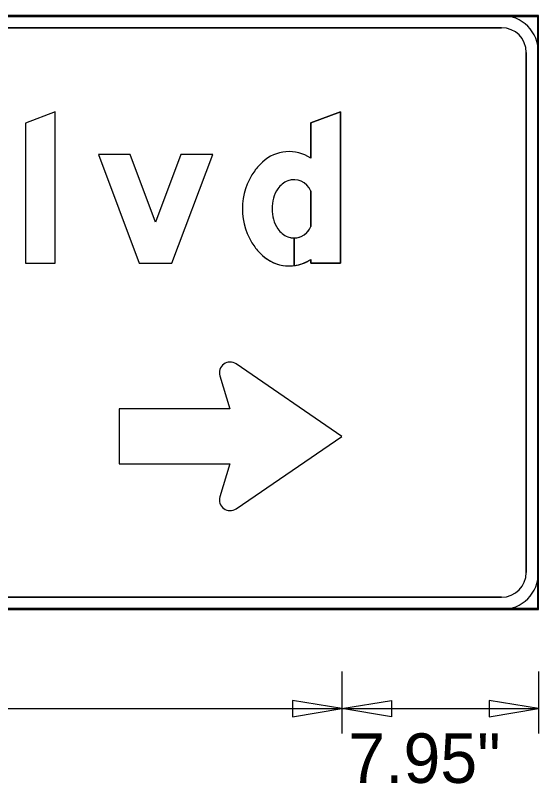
# Model space of a CAD drawing. Extents: x 1374 to 1480, y 568 to 638.
# Drawn here: x 1448.353 to 1450.115, y 598.164 to 600.75 of the extents above; entities that cross this region are included whole.
import ezdxf

# ---------------------------------------------------------------- set-up
doc = ezdxf.new("R2010")
doc.units = 0
for name, color, linetype in [('GSBWFill', 7, 'Continuous'), ('GSColorFill', 7, 'Continuous'), ('GSDims', 7, 'Continuous'), ('GSOutline', 7, 'Continuous')]:
    doc.layers.add(name, color=color, linetype=linetype)

msp = doc.modelspace()

# ---------------------------------------------------------------- linework, layer by layer
at = {"layer": 'GSBWFill'}
for p, q in [((1450.1146, 600.7496), (1441.1146, 600.7496)), ((1449.9896, 600.7496), (1441.2396, 600.7496)), ((1450.1146, 598.7496), (1450.1146, 600.7496)), ((1441.2396, 600.7079), (1449.9896, 600.7079)), ((1450.073, 600.6246), (1450.073, 598.8746)), ((1450.1146, 598.8746), (1450.1146, 600.6246)), ((1449.3471, 600.1585), (1449.3471, 600.0386)), ((1449.2913, 600.0005), (1449.2913, 599.9071)), ((1449.2913, 599.9071), (1449.2913, 600.0005)), ((1449.9896, 598.7912), (1441.24, 598.7912)), ((1441.1146, 598.7496), (1450.1146, 598.7496)), ((1441.24, 598.7496), (1449.9896, 598.7496))]:
    msp.add_line(p, q, dxfattribs=at)
for points in [[(1448.4871, 599.916), (1448.4871, 600.4248), (1448.3871, 600.3869), (1448.3871, 599.916)], [(1448.739, 600.281), (1448.6321, 600.281), (1448.7696, 599.916), (1448.8796, 599.916), (1449.0171, 600.281), (1448.9103, 600.281), (1448.8246, 600.0537)]]:
    msp.add_lwpolyline(points, close=True, dxfattribs=at)
for points in [[(1449.3471, 599.928), (1449.3471, 599.916), (1449.4471, 599.916), (1449.4471, 600.4248), (1449.3471, 600.3879), (1449.3471, 600.2691)], [(1449.0962, 599.089), (1449.4521, 599.3327), (1449.0962, 599.5764)], [(1449.0413, 599.536), (1449.0753, 599.4255), (1448.7021, 599.4255)], [(1448.7021, 599.4255), (1448.7021, 599.2399), (1449.0753, 599.2399), (1449.0413, 599.1294)]]:
    msp.add_lwpolyline(points, dxfattribs=at)
for centre, radius, start, end in [((1449.9896, 600.6246), 0.125, 0, 90), ((1449.9896, 600.6246), 0.0833, 0, 90), ((1449.0758, 599.5466), 0.0361, 55.6003, 197.0573), ((1449.0758, 599.1188), 0.0361, 162.9427, 304.3997), ((1449.9896, 598.8746), 0.125, 270, 0), ((1449.9896, 598.8746), 0.0833, 270, 0)]:
    msp.add_arc(centre, radius, start, end, dxfattribs=at)
for centre, major_axis, start_param, end_param in [((1449.2746, 600.1601), (0, 0.1309), 5.696193, 7.034788), ((1449.2879, 600.1351), (0, 0.1584), 0.704703, 0.952762), ((1449.3358, 600.0985), (0, 0.2187), 0.943678, 1.570796), ((1449.2948, 600.1272), (0, 0.07), 0.364208, 0.979941), ((1449.2913, 600.1365), (0, 0.06), 5.086447, 6.647393), ((1449.3326, 600.1019), (0, 0.1155), 0.979941, 1.599528), ((1449.3358, 600.0985), (0, 0.2187), 1.570796, 2.197914), ((1449.3326, 600.0952), (0, 0.1155), 1.542065, 2.161651), ((1449.2913, 600.0605), (0, 0.06), 3.142009, 4.338331), ((1449.2948, 600.0699), (0, 0.07), 2.161651, 2.777385), ((1449.2913, 600.0605), (0, 0.06), 2.777385, 3.141593), ((1449.2879, 600.062), (0, 0.1584), 2.188831, 2.436889), ((1449.2746, 600.037), (0, 0.1309), 2.38999, 3.269164), ((1449.2746, 600.037), (0, 0.1309), 3.269357, 3.728585)]:
    msp.add_ellipse(centre, major_axis=major_axis, ratio=0.999997, start_param=start_param, end_param=end_param, dxfattribs=at)
at = {"layer": 'GSColorFill'}
for p, q in [((1450.1146, 600.7496), (1441.1146, 600.7496)), ((1450.1146, 600.7496), (1441.1146, 600.7496)), ((1441.1188, 600.7454), (1450.1105, 600.7454)), ((1449.9896, 600.7496), (1441.2396, 600.7496)), ((1450.1105, 600.7454), (1450.1105, 598.7537)), ((1450.1146, 598.7496), (1450.1146, 600.7496)), ((1450.1146, 598.7496), (1450.1146, 600.7496)), ((1441.2396, 600.7079), (1449.9896, 600.7079)), ((1450.073, 600.6246), (1450.073, 598.8746)), ((1450.1146, 598.8746), (1450.1146, 600.6246)), ((1449.3471, 600.1585), (1449.3471, 600.0386)), ((1449.2913, 600.0005), (1449.2913, 599.9071)), ((1449.2913, 599.9071), (1449.2913, 600.0005)), ((1449.9896, 598.7912), (1441.24, 598.7912)), ((1450.1105, 598.7537), (1441.1146, 598.7537)), ((1441.1146, 598.7496), (1450.1146, 598.7496)), ((1441.1146, 598.7496), (1450.1146, 598.7496)), ((1441.24, 598.7496), (1449.9896, 598.7496))]:
    msp.add_line(p, q, dxfattribs=at)
for points in [[(1448.4871, 599.916), (1448.4871, 600.4248), (1448.3871, 600.3869), (1448.3871, 599.916)], [(1448.739, 600.281), (1448.6321, 600.281), (1448.7696, 599.916), (1448.8796, 599.916), (1449.0171, 600.281), (1448.9103, 600.281), (1448.8246, 600.0537)]]:
    msp.add_lwpolyline(points, close=True, dxfattribs=at)
for points in [[(1449.3471, 599.928), (1449.3471, 599.916), (1449.4471, 599.916), (1449.4471, 600.4248), (1449.3471, 600.3879), (1449.3471, 600.2691)], [(1449.0962, 599.089), (1449.4521, 599.3327), (1449.0962, 599.5764)], [(1449.0413, 599.536), (1449.0753, 599.4255), (1448.7021, 599.4255)], [(1448.7021, 599.4255), (1448.7021, 599.2399), (1449.0753, 599.2399), (1449.0413, 599.1294)]]:
    msp.add_lwpolyline(points, dxfattribs=at)
for centre, radius, start, end in [((1449.9896, 600.6246), 0.125, 0, 90), ((1449.9896, 600.6246), 0.0833, 0, 90), ((1449.0758, 599.5466), 0.0361, 55.6003, 197.0573), ((1449.0758, 599.1188), 0.0361, 162.9427, 304.3997), ((1449.9896, 598.8746), 0.125, 270, 0), ((1449.9896, 598.8746), 0.0833, 270, 0)]:
    msp.add_arc(centre, radius, start, end, dxfattribs=at)
for centre, major_axis, start_param, end_param in [((1449.2746, 600.1601), (0, 0.1309), 5.696193, 7.034788), ((1449.2879, 600.1351), (0, 0.1584), 0.704703, 0.952762), ((1449.3358, 600.0985), (0, 0.2187), 0.943678, 1.570796), ((1449.2948, 600.1272), (0, 0.07), 0.364208, 0.979941), ((1449.2913, 600.1365), (0, 0.06), 5.086447, 6.647393), ((1449.3326, 600.1019), (0, 0.1155), 0.979941, 1.599528), ((1449.3358, 600.0985), (0, 0.2187), 1.570796, 2.197914), ((1449.3326, 600.0952), (0, 0.1155), 1.542065, 2.161651), ((1449.2913, 600.0605), (0, 0.06), 3.142009, 4.338331), ((1449.2948, 600.0699), (0, 0.07), 2.161651, 2.777385), ((1449.2913, 600.0605), (0, 0.06), 2.777385, 3.141593), ((1449.2879, 600.062), (0, 0.1584), 2.188831, 2.436889), ((1449.2746, 600.037), (0, 0.1309), 2.38999, 3.269164), ((1449.2746, 600.037), (0, 0.1309), 3.269357, 3.728585)]:
    msp.add_ellipse(centre, major_axis=major_axis, ratio=0.999997, start_param=start_param, end_param=end_param, dxfattribs=at)
at = {"layer": 'GSDims'}
for p, q in [((1449.4521, 598.5412), (1449.4521, 598.3329)), ((1449.4521, 598.5412), (1449.4521, 598.3329)), ((1450.1146, 598.5412), (1450.1146, 598.3329)), ((1450.1146, 598.5412), (1450.1146, 598.3329)), ((1441.7771, 598.4162), (1449.4521, 598.4162)), ((1449.4521, 598.4162), (1450.1146, 598.4162))]:
    msp.add_line(p, q, dxfattribs=at)
for points in [[(1449.4521, 598.4162), (1449.2855, 598.444), (1449.2855, 598.3884)], [(1449.4521, 598.4162), (1449.6188, 598.444), (1449.6188, 598.3884)], [(1450.1146, 598.4162), (1449.948, 598.444), (1449.948, 598.3884)]]:
    msp.add_lwpolyline(points, close=True, dxfattribs=at)
at = {"layer": 'GSOutline'}
for p, q in [((1450.1146, 600.7496), (1441.1146, 600.7496)), ((1449.9896, 600.7496), (1441.2396, 600.7496)), ((1450.1146, 598.7496), (1450.1146, 600.7496)), ((1449.9896, 600.7079), (1441.2396, 600.7079)), ((1450.073, 598.8746), (1450.073, 600.6246)), ((1450.1146, 598.8746), (1450.1146, 600.6246)), ((1449.3471, 600.0386), (1449.3471, 600.1585)), ((1441.2396, 598.7912), (1449.9896, 598.7912)), ((1441.1146, 598.7496), (1450.1146, 598.7496)), ((1441.2396, 598.7496), (1449.9896, 598.7496))]:
    msp.add_line(p, q, dxfattribs=at)
for points in [[(1448.4871, 599.916), (1448.4871, 600.4248), (1448.3871, 600.3869), (1448.3871, 599.916)], [(1448.739, 600.281), (1448.6321, 600.281), (1448.7696, 599.916), (1448.8796, 599.916), (1449.0171, 600.281), (1448.9103, 600.281), (1448.8246, 600.0537)]]:
    msp.add_lwpolyline(points, close=True, dxfattribs=at)
for points in [[(1449.3471, 600.2691), (1449.3471, 600.3879), (1449.4471, 600.4248), (1449.4471, 599.916), (1449.3471, 599.916), (1449.3471, 599.928)], [(1449.0962, 599.089), (1449.4521, 599.3327), (1449.0962, 599.5764)], [(1449.0413, 599.536), (1449.0753, 599.4255), (1448.7021, 599.4255)], [(1448.7021, 599.4255), (1448.7021, 599.2399), (1449.0753, 599.2399), (1449.0413, 599.1294)]]:
    msp.add_lwpolyline(points, dxfattribs=at)
for centre, radius, start, end in [((1449.9896, 600.6246), 0.125, 0, 90), ((1449.9896, 600.6246), 0.0833, 0, 90), ((1449.0758, 599.5466), 0.0361, 55.6003, 197.0573), ((1449.0758, 599.1188), 0.0361, 162.9427, 304.3997), ((1449.9896, 598.8746), 0.125, 270, 0), ((1449.9896, 598.8746), 0.0833, 270, 0)]:
    msp.add_arc(centre, radius, start, end, dxfattribs=at)
for centre, major_axis, start_param, end_param in [((1449.2746, 600.1601), (0, 0.1309), 5.696193, 7.034788), ((1449.2879, 600.1351), (0, 0.1584), 0.704703, 0.952762), ((1449.3358, 600.0985), (0, 0.2187), 0.943678, 1.570796), ((1449.2948, 600.1272), (0, 0.07), 0.364208, 0.979941), ((1449.2913, 600.1365), (0, 0.06), 5.086447, 6.647393), ((1449.3326, 600.1019), (0, 0.1155), 0.979941, 1.599528), ((1449.3358, 600.0985), (0, 0.2187), 1.570796, 2.197914), ((1449.3326, 600.0952), (0, 0.1155), 1.542065, 2.161651), ((1449.2913, 600.0605), (0, 0.06), 2.777385, 4.338331), ((1449.2948, 600.0699), (0, 0.07), 2.161651, 2.777385), ((1449.2879, 600.062), (0, 0.1584), 2.188831, 2.436889), ((1449.2746, 600.037), (0, 0.1309), 2.38999, 3.728585)]:
    msp.add_ellipse(centre, major_axis=major_axis, ratio=0.999997, start_param=start_param, end_param=end_param, dxfattribs=at)

# ---------------------------------------------------------------- texts
at = {"layer": 'GSDims'}
msp.add_text('7.95"', height=0.16667, dxfattribs=at).set_placement((1449.4738, 598.1662))

doc.saveas('drawing.dxf')
